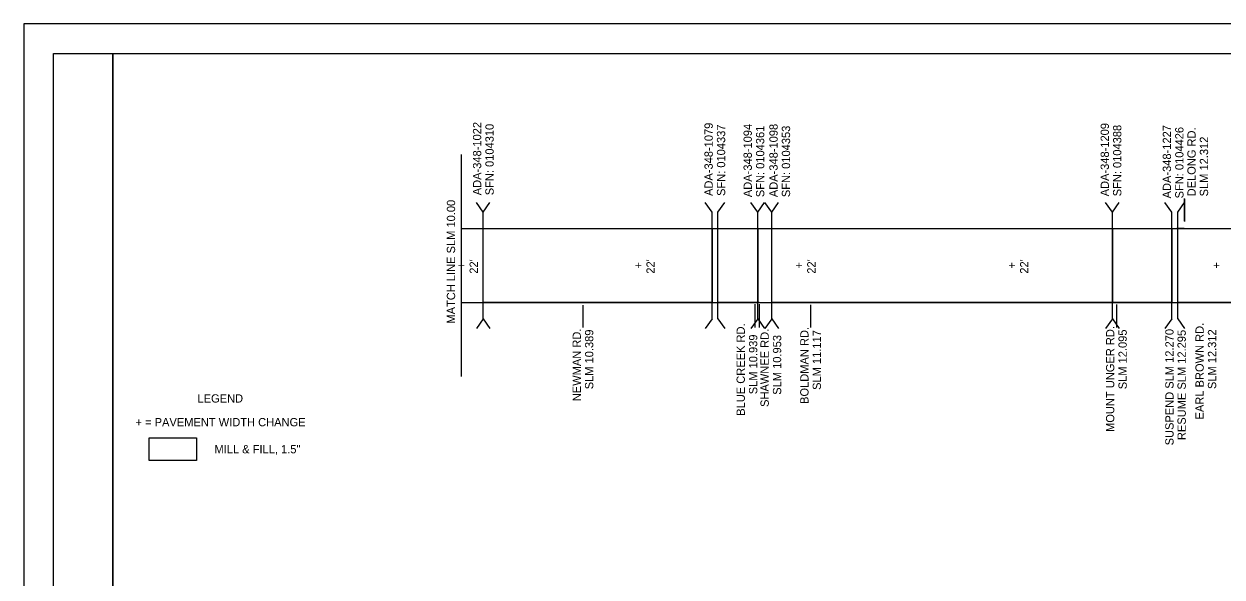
# Model space of a CAD drawing. Extents: x 0 to 34, y 0 to 22.
# Drawn here: x 0 to 20.23, y 12.66 to 22 of the extents above; entities that cross this region are included whole.
import ezdxf

# ---------------------------------------------------------------- set-up
doc = ezdxf.new("R2010")
doc.units = 0
for name, color, linetype in [('Default', 7, 'Continuous'), ('SH_Border', 7, 'Continuous'), ('SH_Cut_Line', 7, 'Continuous'), ('SH_Text', 7, 'Continuous'), ('TX_P_1', 7, 'Continuous')]:
    doc.layers.add(name, color=color, linetype=linetype)

msp = doc.modelspace()

# ---------------------------------------------------------------- linework, layer by layer
at = {"layer": 'Default'}
for q in [(32, 21.5), (1.5, 0.66)]:
    msp.add_line((1.5, 21.5), q, dxfattribs=at)
for points in [[(7.753, 18.545), (11.618, 18.545), (11.618, 17.295), (7.753, 17.295)], [(12.389, 17.295), (11.718, 17.295), (11.718, 18.545), (12.389, 18.545)], [(18.377, 17.295), (12.627, 17.295), (12.627, 18.545), (18.377, 18.545)], [(19.38, 17.295), (18.377, 17.295), (18.377, 18.545), (19.38, 18.545)], [(19.48, 18.545), (21.761, 18.545), (21.761, 17.295), (19.48, 17.295)], [(2.112, 15.007), (2.912, 15.007), (2.912, 14.628), (2.112, 14.628)], [(2.112, 15.007), (2.912, 15.007), (2.912, 14.628), (2.112, 14.628)]]:
    msp.add_lwpolyline(points, close=True, dxfattribs=at)
at = {"layer": 'SH_Border'}
for points in [[(0.5, 21.5), (1.5, 21.5), (1.5, 0.5), (0.5, 0.5)], [(1.5, 21.5), (33.5, 21.5), (33.5, 0.5), (1.5, 0.5)]]:
    msp.add_lwpolyline(points, close=True, dxfattribs=at)
at = {"layer": 'SH_Cut_Line'}
msp.add_lwpolyline([(0, 0), (34, 0), (34, 22), (0, 22)], close=True, dxfattribs=at)
at = {"layer": 'SH_Text'}
for p, q in [((7.384, 19.795), (7.384, 16.045)), ((19.591, 19.054), (19.591, 18.67)), ((19.593, 19.047), (19.593, 18.662)), ((7.753, 18.82), (7.639, 18.983)), ((7.753, 18.82), (7.868, 18.983)), ((7.753, 17.02), (7.753, 18.82)), ((11.618, 18.82), (11.504, 18.983)), ((11.618, 17.02), (11.618, 18.82)), ((11.718, 18.82), (11.833, 18.983)), ((11.718, 17.02), (11.718, 18.82)), ((12.389, 18.82), (12.275, 18.983)), ((12.389, 18.82), (12.504, 18.983)), ((12.389, 17.02), (12.389, 18.82)), ((12.627, 18.82), (12.512, 18.983)), ((12.627, 18.82), (12.742, 18.983)), ((12.627, 17.02), (12.627, 18.82)), ((18.377, 18.82), (18.262, 18.983)), ((18.377, 18.82), (18.492, 18.983)), ((18.377, 17.02), (18.377, 18.82)), ((19.38, 18.82), (19.265, 18.983)), ((19.38, 17.02), (19.38, 18.82)), ((19.48, 18.82), (19.595, 18.983)), ((19.48, 17.02), (19.48, 18.82)), ((7.384, 18.545), (26.128, 18.545)), ((19.591, 18.545), (19.466, 18.545)), ((19.591, 18.545), (19.716, 18.545)), ((7.384, 17.295), (26.128, 17.295)), ((9.438, 17.295), (9.313, 17.295)), ((9.438, 17.295), (9.563, 17.295)), ((9.438, 17.25), (9.438, 16.87)), ((12.342, 17.295), (12.217, 17.295)), ((12.416, 17.295), (12.291, 17.295)), ((12.342, 17.295), (12.467, 17.295)), ((12.342, 17.268), (12.342, 16.87)), ((12.416, 17.295), (12.541, 17.295)), ((12.416, 17.268), (12.416, 16.87)), ((13.282, 17.295), (13.157, 17.295)), ((13.282, 17.295), (13.407, 17.295)), ((13.282, 17.254), (13.282, 16.87)), ((18.445, 17.295), (18.32, 17.295)), ((18.445, 17.295), (18.57, 17.295)), ((18.445, 17.263), (18.445, 16.87)), ((7.753, 17.02), (7.639, 16.856)), ((7.753, 17.02), (7.868, 16.856)), ((11.618, 17.02), (11.504, 16.856)), ((11.718, 17.02), (11.833, 16.856)), ((12.389, 17.02), (12.275, 16.856)), ((12.389, 17.02), (12.504, 16.856)), ((12.627, 17.02), (12.512, 16.856)), ((12.627, 17.02), (12.742, 16.856)), ((18.377, 17.02), (18.262, 16.856)), ((18.377, 17.02), (18.492, 16.856)), ((19.38, 17.02), (19.265, 16.856)), ((19.48, 17.02), (19.595, 16.856))]:
    msp.add_line(p, q, dxfattribs=at)
at = {"layer": 'TX_P_1'}
msp.add_lwpolyline([(2.112, 15.007), (2.912, 15.007), (2.912, 14.628), (2.112, 14.628)], close=True, dxfattribs=at)

# ---------------------------------------------------------------- texts
at = {"layer": 'SH_Text'}
for s, p in [('ADA-348-1022', (7.721, 19.106)), ('SFN: 0104310', (7.931, 19.106)), ('ADA-348-1079', (11.63, 19.094)), ('SFN: 0104337', (11.84, 19.094)), ('ADA-348-1094', (12.29, 19.074)), ('SFN: 0104361', (12.5, 19.074)), ('ADA-348-1098', (12.726, 19.074)), ('SFN: 0104353', (12.936, 19.074)), ('ADA-348-1209', (18.319, 19.088)), ('SFN: 0104388', (18.529, 19.088)), ('ADA-348-1227', (19.368, 19.053)), ('SFN: 0104426', (19.578, 19.053)), ('DELONG RD.', (19.784, 19.087)), ('SLM 12.312', (19.994, 19.087)), ('MATCH LINE SLM 10.00', (7.28, 16.938)), ("22'", (7.664, 17.781)), ("22'", (10.65, 17.781)), ("22'", (13.365, 17.781)), ("22'", (16.959, 17.781)), ('+', (7.454, 17.867)), ('+', (10.44, 17.867)), ('+', (13.155, 17.867)), ('+', (16.749, 17.867)), ('+', (20.204, 17.867)), ('NEWMAN RD.', (9.403, 15.627)), ('SLM 10.389', (9.613, 15.828)), ('BLUE CREEK RD.', (12.172, 15.381)), ('SHAWNEE RD.', (12.576, 15.53)), ('BOLDMAN RD.', (13.247, 15.581)), ('SLM 11.117', (13.457, 15.818)), ('MOUNT UNGER RD.', (18.41, 15.108)), ('SLM 12.095', (18.62, 15.829)), ('SUSPEND SLM 12.270', (19.411, 14.881)), ('RESUME SLM 12.295', (19.617, 14.97)), ('EARL BROWN RD.', (19.92, 15.319)), ('SLM 12.312', (20.13, 15.832)), ('SLM 10.939', (12.382, 15.744)), ('SLM 10.953', (12.786, 15.736))]:
    msp.add_text(s, height=0.14, rotation=90, dxfattribs=at).set_placement(p)
at = {"layer": 'TX_P_1'}
for s, p in [('LEGEND', (2.93, 15.604)), ('+ = PAVEMENT WIDTH CHANGE', (1.884, 15.203)), ('MILL & FILL, 1.5"', (3.217, 14.747))]:
    msp.add_text(s, height=0.14, dxfattribs=at).set_placement(p)

doc.saveas('drawing.dxf')
